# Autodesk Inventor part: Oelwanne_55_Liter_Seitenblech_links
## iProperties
Created: 2005-05
Part Number: Oelwanne_55_Liter_Seitenblech_links
Document SubType Name: Sheet Metal
Designer: Mario Wipf
Manufacturer: Standard
Standards Organization: Custom
Author: Mario Wipf
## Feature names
1. Extrusion1
2. Extrusion2
3. Spiegeln1 [Mirror]
4. Grobblech1
5. Grobblech2
6. Biegung1
7. Grobblech3
8. Biegung2
